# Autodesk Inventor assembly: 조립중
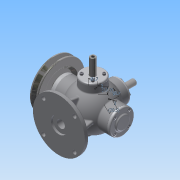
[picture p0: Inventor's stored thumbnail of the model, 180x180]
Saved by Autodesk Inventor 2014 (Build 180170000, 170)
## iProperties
Created: 2016-01
Part Number: 조립중
Document SubType Name: Assembly
Designer: Administrator
Author: Administrator
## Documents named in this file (17)
- C:\Users\Administrator\Desktop\360108V1014\조립중.iam
- C:\Users\Administrator\Desktop\360108V1014\본체.ipt
- C:\Users\Administrator\Desktop\360108V1014\앞커버.ipt
- C:\Users\Administrator\Desktop\360108V1014\뒤커버.ipt
- C:\Users\Administrator\Desktop\360108V1014\베어링- 6202.ipt
- C:\Users\Administrator\Desktop\360108V1014\축.ipt
- C:\Users\Administrator\Desktop\360108V1014\본체커버.ipt
- C:\Users\Administrator\Desktop\360108V1014\볼트 M4x0.7.ipt
- C:\Users\Administrator\Desktop\360108V1014\슬라이드.ipt
- C:\Users\Administrator\Desktop\360108V1014\키-4x4.ipt
- C:\Users\Administrator\Desktop\360108V1014\오일실.ipt
- C:\Users\Administrator\Desktop\360108V1014\슬라이드 커버.ipt
- C:\Users\Administrator\Desktop\360108V1014\V-벨트풀리.ipt
- C:\Users\Administrator\Desktop\360108V1014\너트-M8x1.ipt
- C:\Users\Administrator\Desktop\360108V1014\와셔 8x17.ipt
- C:\Users\Administrator\Desktop\360108V1014\가변스프링.ipt
- C:\Users\Administrator\Desktop\360108V1014\가변스프링2.ipt
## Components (20 placed, 4 different names)
1. M4x0.7x12:5
2. V-벨트풀리:1 — 플러쉬:1, 각도:2
3. 가변스프링:1
4. 가변스프링2:1
5. M4x0.7x12:1
6. M4x0.7x12:2
7. M4x0.7x12:3
8. M4x0.7x12:4
9. M4x0.7x12:6
10. M4x0.7x12:7
11. M4x0.7x12:8
12. M4x0.7x12:9
13. M4x0.7x12:10
14. M4x0.7x12:11
15. M4x0.7x12:12
16. M4x0.7x12:13
17. M4x0.7x12:14
18. M4x0.7x12:15
19. M4x0.7x12:16
20. M4x0.7x12:17
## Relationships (2: Flush 1, Angle 1)
- 플러쉬:1 [Flush]: V-벨트풀리:1
- 각도:2 [Angle]: V-벨트풀리:1
